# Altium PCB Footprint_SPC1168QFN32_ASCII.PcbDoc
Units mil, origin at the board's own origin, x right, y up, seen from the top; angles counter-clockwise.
Board outline 6000 x 4000 mil, 2 copper layers (Top Layer, Bottom Layer); 1 components, 0 nets, 37 pads, 9 vias.
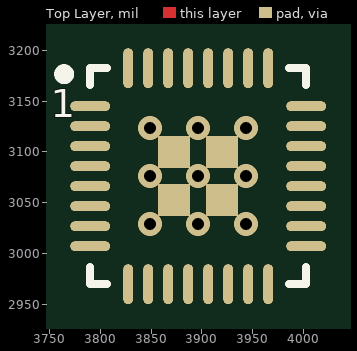
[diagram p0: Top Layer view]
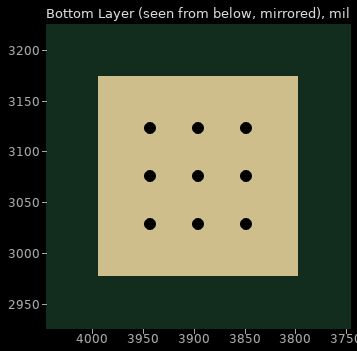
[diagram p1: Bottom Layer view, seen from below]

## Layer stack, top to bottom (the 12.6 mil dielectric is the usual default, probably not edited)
Top Solder: solder mask 0.4, Solder Resist, Dk 3.5
Top Layer: signal copper 1.4
Dielectric 1: dielectric 12.6, FR-4, Dk 4.8
Bottom Layer: signal copper 1.4
Bottom Solder: solder mask 0.4, Solder Resist, Dk 3.5

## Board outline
1000,1000 7000,1000 7000,5000 1000,5000

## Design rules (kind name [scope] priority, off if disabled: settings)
AssemblyTestPointUsage [All] p0: scope1count=1 scope1_0_kind=Board scope1_0_value=Board scope2count=1 scope2_0_kind=Board scope2_0_value=Board commentlength=0
AssemblyTestpoint [All] p0: scope1count=1 scope1_0_kind=Board scope1_0_value=Board scope2count=1 scope2_0_kind=Board scope2_0_value=Board commentlength=0
Clearance [All] p0: scope1count=1 scope1_0_kind=Board scope1_0_value=Board scope2count=1 scope2_0_kind=Board scope2_0_value=Board commentlength=0 gap=10
Clearance [All] p1: gap=10 ignorepadtopadclearanceinfootprint=FALSE except(0: Arc-Hole Track-Hole SMDPad-Hole THPad-Hole Via-Hole Fill-Hole Poly-Hole Region-Hole Text-Hole)
ComponentClearance [All] p0: scope1count=1 scope1_0_kind=Board scope1_0_value=Board scope2count=1 scope2_0_kind=Board scope2_0_value=Board commentlength=0 gap=10 collisioncheckmode=3
DiffPairsRouting [All] p0: scope1count=1 scope1_0_kind=Board scope1_0_value=Board scope2count=1 scope2_0_kind=Board scope2_0_value=Board commentlength=0
FabricationTestPointUsage [All] p0: scope1count=1 scope1_0_kind=Board scope1_0_value=Board scope2count=1 scope2_0_kind=Board scope2_0_value=Board commentlength=0 valid=0 allowmultiple=FALSE
FabricationTestpoint [All] p0: scope1count=1 scope1_0_kind=Board scope1_0_value=Board scope2count=1 scope2_0_kind=Board scope2_0_value=Board commentlength=0 side=3 testpointundercomponent=TRUE minsize=40 maxsize=100 preferedsize=60 minholesize=0 maxholesize=40 preferedholesize=32 testpointgrid=1
FanoutControl Fanout_BGA [All] p0 off: scope1count=1 scope1_0_kind=Board scope1_0_value=Board scope2count=1 scope2_0_kind=Board scope2_0_value=Board commentlength=69 // Protel DXP Scope 1 Expression Was: IsBGA   Fanout_BGA (Default Rule)
FanoutControl Fanout_LCC [All] p0 off: scope1count=1 scope1_0_kind=Board scope1_0_value=Board scope2count=1 scope2_0_kind=Board scope2_0_value=Board commentlength=69 // Protel DXP Scope 1 Expression Was: IsLCC   Fanout_LCC (Default Rule)
FanoutControl Fanout_SOIC [All] p0 off: scope1count=1 scope1_0_kind=Board scope1_0_value=Board scope2count=1 scope2_0_kind=Board scope2_0_value=Board commentlength=71 // Protel DXP Scope 1 Expression Was: IsSOIC   Fanout_SOIC (Default Rule)
FanoutControl Fanout_Small [All] p0 off: scope1count=1 scope1_0_kind=Board scope1_0_value=Board scope2count=1 scope2_0_kind=Board scope2_0_value=Board commentlength=84 // Protel DXP Scope 1 Expression Was: (CompPinCount < 5)   Fanout_Small (Default Rule)
FanoutControl Fanout_Default [All] p0: scope1count=1 scope1_0_kind=Board scope1_0_value=Board scope2count=1 scope2_0_kind=Board scope2_0_value=Board commentlength=30 // Fanout_Default (Default Rule)
Height [All] p0: scope1count=1 scope1_0_kind=Board scope1_0_value=Board scope2count=1 scope2_0_kind=Board scope2_0_value=Board commentlength=0
HoleSize [All] p0: scope1count=1 scope1_0_kind=Board scope1_0_value=Board scope2count=1 scope2_0_kind=Board scope2_0_value=Board commentlength=0 absolutevalues=TRUE maxlimit=100 minlimit=1 maxpercent=80.000 minpercent=20.000
HoleToHoleClearance [All] p0: scope1count=1 scope1_0_kind=Board scope1_0_value=Board scope2count=1 scope2_0_kind=Board scope2_0_value=Board commentlength=0
LayerPairs [All] p0: scope1count=1 scope1_0_kind=Board scope1_0_value=Board scope2count=1 scope2_0_kind=Board scope2_0_value=Board commentlength=0 enforce=TRUE
MinimumSolderMaskSliver [All] p0: scope1count=1 scope1_0_kind=Board scope1_0_value=Board scope2count=1 scope2_0_kind=Board scope2_0_value=Board commentlength=0
NetAntennae [All] p0: scope1count=1 scope1_0_kind=Board scope1_0_value=Board scope2count=1 scope2_0_kind=Board scope2_0_value=Board commentlength=0
PasteMaskExpansion [All] p0: scope1count=1 scope1_0_kind=Board scope1_0_value=Board scope2count=1 scope2_0_kind=Board scope2_0_value=Board commentlength=0 expansion=0
PlaneClearance [All] p0: scope1count=1 scope1_0_kind=Board scope1_0_value=Board scope2count=1 scope2_0_kind=Board scope2_0_value=Board commentlength=0 clearance=20
PlaneConnect [All] p0: scope1count=1 scope1_0_kind=Board scope1_0_value=Board scope2count=1 scope2_0_kind=Board scope2_0_value=Board commentlength=0 planeconnectstyle=Relief reliefexpansion=20 reliefentries=4 reliefconductorwidth=10 reliefairgap=10
PolygonConnect [All] p0: scope1count=1 scope1_0_kind=Board scope1_0_value=Board scope2count=1 scope2_0_kind=Board scope2_0_value=Board commentlength=0 connectstyle=Relief reliefconductorwidth=10 reliefentries=4 polygonreliefangle="90 Angle"
PolygonConnect [All] p1: connectstyle=Relief reliefconductorwidth=10 reliefentries=4 polygonreliefangle="90 Angle" airgapwidth=10
RoutingCorners [All] p0: scope1count=1 scope1_0_kind=Board scope1_0_value=Board scope2count=1 scope2_0_kind=Board scope2_0_value=Board commentlength=0 cornerstyle=45-Degree minsetback=100 maxsetback=100
RoutingLayers [All] p0: scope1count=1 scope1_0_kind=Board scope1_0_value=Board scope2count=1 scope2_0_kind=Board scope2_0_value=Board commentlength=0 top layer=Automatic bottom layer=Automatic
RoutingPriority [All] p0: scope1count=1 scope1_0_kind=Board scope1_0_value=Board scope2count=1 scope2_0_kind=Board scope2_0_value=Board commentlength=0
RoutingTopology [All] p0: scope1count=1 scope1_0_kind=Board scope1_0_value=Board scope2count=1 scope2_0_kind=Board scope2_0_value=Board commentlength=0 topology=Shortest
RoutingVias [All] p0: scope1count=1 scope1_0_kind=Board scope1_0_value=Board scope2count=1 scope2_0_kind=Board scope2_0_value=Board commentlength=0 holewidth=28 width=50 viastyle="Through Hole" minholewidth=28 minwidth=50 maxholewidth=28 maxwidth=50
RoutingVias [All] p1: holewidth=28 width=50 viastyle="Through Hole" minholewidth=28 minwidth=50 maxholewidth=28 maxwidth=50
ShortCircuit [All] p0: scope1count=1 scope1_0_kind=Board scope1_0_value=Board scope2count=1 scope2_0_kind=Board scope2_0_value=Board commentlength=0 allowed=FALSE
SilkToBoardRegionClearance [All] p0: scope1count=1 scope1_0_kind=Board scope1_0_value=Board scope2count=1 scope2_0_kind=Board scope2_0_value=Board commentlength=0
SilkToSilkClearance [All] p0: scope1count=1 scope1_0_kind=Board scope1_0_value=Board scope2count=1 scope2_0_kind=Board scope2_0_value=Board commentlength=0
SilkToSolderMaskClearance [All] p0 off: scope1count=1 scope1_0_kind=Board scope1_0_value=Board scope2count=1 scope2_0_kind=Board scope2_0_value=Board commentlength=44 // Protel DXP Scope 1 Expression Was: IsPad
SolderMaskExpansion [All] p0: scope1count=1 scope1_0_kind=Board scope1_0_value=Board scope2count=1 scope2_0_kind=Board scope2_0_value=Board commentlength=0 expansion=4
SolderMaskExpansion [All] p1: expansion=4 istentingtop=FALSE
UnRoutedNet [All] p0: scope1count=1 scope1_0_kind=Board scope1_0_value=Board scope2count=1 scope2_0_kind=Board scope2_0_value=Board commentlength=0
UnpouredPolygon [All] p0: scope1count=1 scope1_0_kind=Board scope1_0_value=Board scope2count=1 scope2_0_kind=Board scope2_0_value=Board commentlength=0
Width [All] p0: scope1count=1 scope1_0_kind=Board scope1_0_value=Board scope2count=1 scope2_0_kind=Board scope2_0_value=Board commentlength=0 maxlimit=10 minlimit=10 preferedwidth=10
Width [All] p1: maxlimit=10 minlimit=10 preferedwidth=10
30 further rules are at their usual default settings.

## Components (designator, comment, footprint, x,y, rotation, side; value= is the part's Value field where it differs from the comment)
? "Comment" QFN-32-0.5 3790,3145 r0 top

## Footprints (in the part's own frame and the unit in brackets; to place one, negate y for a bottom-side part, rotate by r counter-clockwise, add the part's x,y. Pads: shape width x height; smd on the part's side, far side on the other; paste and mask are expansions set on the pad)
QFN-32-0.5 [mm] "P-0.5,5*5mm"
  oval 1x0.25 smd: 1(0,0) 2(0,-0.5) 3(0,-1) 4(0,-1.5) 5(0,-2) 6(0,-2.5) 7(0,-3) 8(0,-3.5) 17(5.4,-3.5) 18(5.4,-3) 19(5.4,-2.5) 20(5.4,-2) 21(5.4,-1.5) 22(5.4,-1) 23(5.4,-0.5) 24(5.4,0)
  oval 0.25x1 smd: 9(0.95,-4.45) 10(1.45,-4.45) 11(1.95,-4.45) 12(2.45,-4.45) 13(2.95,-4.45) 14(3.45,-4.45) 15(3.95,-4.45) 16(4.45,-4.45) 25(4.45,0.95) 26(3.95,0.95) 27(3.45,0.95) 28(2.95,0.95) 29(2.45,0.95) 30(1.95,0.95) 31(1.45,0.95) 32(0.95,0.95)
  rect 0.8x0.8 smd: A(2.1,-1.15) B(3.3,-1.15) C(2.1,-2.35) D(3.3,-2.35)
  rect 5x5 smd far side: E(2.7,-1.75)
  Mechanical 10 keep-out region: 0.95,-3.51 4.46,-3.51 4.46,0 0.95,0
  silkscreen extent -0.77,-4.45 5.4,0.95

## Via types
v1: diameter 23.62, hole 11.81, Top Layer to Bottom Layer, 9 vias

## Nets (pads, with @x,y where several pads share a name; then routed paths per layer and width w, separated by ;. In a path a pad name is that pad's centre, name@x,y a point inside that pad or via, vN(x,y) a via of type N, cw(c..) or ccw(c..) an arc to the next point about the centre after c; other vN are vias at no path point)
pads on no net: ?.1 ?.2 ?.3 ?.4 ?.5 ?.6 ?.7 ?.8 ?.9 ?.10 ?.11 ?.12 ?.13 ?.14 ?.15 ?.16 ?.17 ?.18 ?.19 ?.20 ?.21 ?.22 ?.23 ?.24 ?.25 ?.26 ?.27 ?.28 ?.29 ?.30 ?.31 ?.32 ?.A ?.B ?.C ?.D ?.E
copper on no net:
  other v1: 3849.06,3028.86 3896.3,3028.86 3943.54,3028.86 3849.06,3076.1 3896.3,3076.1 3943.54,3076.1 3849.06,3123.35 3896.3,3123.35 3943.55,3123.35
